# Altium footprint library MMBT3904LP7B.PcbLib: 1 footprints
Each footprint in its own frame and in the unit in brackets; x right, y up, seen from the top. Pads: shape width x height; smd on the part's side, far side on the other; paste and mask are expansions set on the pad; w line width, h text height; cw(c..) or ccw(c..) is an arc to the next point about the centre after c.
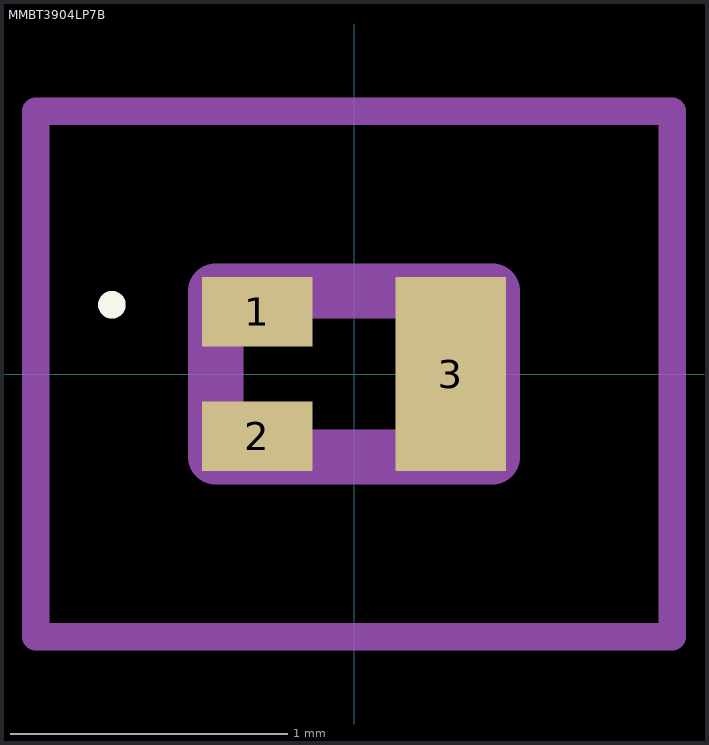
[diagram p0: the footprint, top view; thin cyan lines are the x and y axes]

## MMBT3904LP7B [mm]
pads (3):
  rect 0.4x0.25 smd: 1(-0.35,0.225) 2(-0.35,-0.225)
  rect 0.4x0.7 smd: 3(0.35,0)
Top Overlay:
  lines w0.05: -0.9,0.25 cw(c-0.875,0.25) -0.85,0.25 ; -0.9,0.25 -0.9,0.25 ; -0.9,0.25 ccw(c-0.875,0.25) -0.85,0.25 ; -0.85,0.25 -0.85,0.25
Mechanical 15:
  lines w0.2: -0.5,-0.3 0.5,-0.3 0.5,0.3 -0.5,0.3 -0.5,-0.3
Mechanical 20:
  lines w0.1: -1.15,-0.95 1.15,-0.95 1.15,0.95 -1.15,0.95 -1.15,-0.95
